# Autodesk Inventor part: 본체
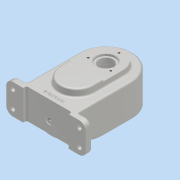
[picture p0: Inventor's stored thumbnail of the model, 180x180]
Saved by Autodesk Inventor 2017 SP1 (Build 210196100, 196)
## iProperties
Part Number: 본체
Material: 알루미늄 6061
Document SubType Name: Modeling
Designer: MRC
Density: 2.7 g/cm^3
Appearance: 알루미늄 - 평지
Mass: 756.756 g
Surface Area: 581.797 cm^2
Volume: 280.28 cm^3
Author: MRC
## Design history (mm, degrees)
sketch "스케치14"
  geometry: L1 (0, 0)-(0, -45); L2 (-40, 0)-(-40, -45); L3 (40, -45)-(40, 0); L4 (0, 0)-(45, 0); L5 (40, -45)-(40, -82); L6 (40, -82)-(61, -82); L7 (61, -82)-(61, -92); L8 (61, -92)-(-61, -92); L9 (-61, -92)-(-61, -82); L10 (-61, -82)-(-40, -82); L11 (-40, -82)-(-40, -45); A1 r 40 centre (0, 0) between (40, 0) and (-40, 0); A2 r 40 centre (0, -45) between (-40, -45) and (40, -45); 1 further point
  constraints: 24 end point, 5 tangent, 4 perpendicular, 4 point on circle, 2 centre point, 2 equal length, 2 point on line, 2 vertical, 1 collinear, 1 horizontal, 1 midpoint, 1 parallel
  dimensions: "d58" = 45 distance of L1.start L1.end; "d59" = 90 deg angle of L1 L4 (derived); "d60" = 80 diameter of A2; "d61" = 47 distance from line of L8 L1.end; "d62" = 122 distance of L7.end L8.end; "d63" = 10 distance of L6.end L7.end
extrude "돌출11" new body sketch "스케치14" distance "d64" = 46; taper "d65" = 0 deg
sketch "스케치15"
  geometry: L1 (0, 0)-(0, -45); L2 (-40, 0)-(-40, -45); L3 (40, -45)-(40, 0); A1 r 40 centre (0, 0) between (40, 0) and (-40, 0) reference; A2 r 40 centre (0, 0) between (40, 0) and (-40, 0); A3 r 40 centre (0, -45) between (-40, -45) and (40, -45); 1 further point
  constraints: 8 end point, 4 point on circle, 4 tangent, 2 centre point, 1 midpoint, 1 parallel, 1 vertical
  dimensions: "d66" = 45 distance of L1.start L1.end; "d67" = 40 radius of A3
extrude "돌출12" join sketch "스케치15" distance "d68" = 3; taper "d69" = 0 deg
sketch "스케치16"
  geometry: L1 (0, 0)-(0, -45); L2 (-30, 0)-(-30, -45); L3 (30, -45)-(30, 0); A1 r 40 centre (0, -45) between (-40, -45) and (40, -45) reference; A2 r 40 centre (0, 0) between (40, 0) and (-40, 0) reference; A3 r 30 centre (0, 0) between (30, 0) and (-30, 0); A4 r 30 centre (0, -45) between (-30, -45) and (30, -45); 1 further point
  constraints: 8 end point, 4 point on circle, 4 tangent, 2 centre point, 1 midpoint, 1 parallel, 1 vertical
  dimensions: "d70" = 30 radius of A3
extrude "돌출13" cut sketch "스케치16" distance "d71" = 41; taper "d72" = 0 deg
sketch "스케치17"
  geometry: L1 (0, 0)-(0, -45); L2 (-26, 0)-(-26, -45); L3 (26, -45)-(26, 0); A1 r 40 centre (0, 0) between (40, 0) and (-40, 0) reference; A2 r 26 centre (0, 0) between (26, 0) and (-26, 0); A3 r 26 centre (0, -45) between (-26, -45) and (26, -45); 1 further point
  constraints: 8 end point, 4 point on circle, 4 tangent, 2 centre point, 1 midpoint, 1 parallel, 1 vertical
  dimensions: "d73" = 45 distance of L1.start L1.end; "d74" = 52 diameter of A3
extrude "돌출14" join sketch "스케치17" distance "d75" = 11; taper "d76" = 0 deg
sketch "스케치18"
  geometry: L1 (-26, 0)-(-26, -45) reference; L2 (26, -45)-(26, 0) reference; L3 (-26, -30)-(26, -30); A1 r 26 centre (0, 0) between (26, 0) and (-26, 0) reference
  constraints: 2 end point, 2 point on line, 1 perpendicular
  dimensions: "d77" = 30 distance from line of A1.centre L3
extrude "돌출15" cut sketch "스케치18" distance "d78" = 3; taper "d79" = 0 deg
hole "구멍1" diameter "d82" = 22; stored, may be unused: countersink angle "d86" = 90 deg, drill point angle "d88" = 118 deg; dims "d80" = 10, "d81" = 10, "d83" = 6, "d84" = 28, "d85" = 8, "d87" = 8
hole "구멍2" diameter "d91" = 20; stored, may be unused: countersink angle "d95" = 90 deg, drill point angle "d97" = 0 deg; dims "d89" = 10, "d90" = 10, "d92" = 6, "d93" = 28, "d94" = 8, "d96" = 12
sketch "스케치19"
  geometry: C1 r 11 at (0, 0) reference; C2 r 14 at (0, 0); A1 r 26 centre (0, 0) between (26, 0) and (-26, 0) reference
  constraints: 1 centre point, 1 coincident
  dimensions: "d98" = 28 diameter of C2
extrude "돌출16" cut sketch "스케치19" distance "d99" = 4; taper "d100" = 0 deg
chamfer "모따기4" distance "d101" = 1; stored, may be unused: second distance "d102" = 2, angle "d103" = 45 deg
fillet "모깎기5" dims "d104" = 0.3
fillet "모깎기6" dims "d105" = 3
sketch "스케치20"
  geometry: A1 r 30 centre (0, 0) between (30, 0) and (-30, 0) reference; 1 further point
  constraints: 1 vertical alignment
  dimensions: "d106" = 35 distance of A1.centre point (0, 35)
sketch "스케치21"
  geometry: A1 r 30 centre (0, -45) between (-30, -45) and (30, -45) reference; 1 further point
  constraints: 1 vertical alignment
  dimensions: "d107" = 35 distance of A1.centre point (0, -80)
hole "구멍3" sketch "스케치20" diameter "d108" = 3.242; stored, may be unused: countersink angle "d112" = 90 deg, drill point angle "d114" = 118 deg; dims "d109" = 8, "d110" = 28, "d111" = 8, "d113" = 10
hole "구멍4" sketch "스케치21" diameter "d115" = 3.242; stored, may be unused: countersink angle "d119" = 90 deg, drill point angle "d121" = 118 deg; dims "d116" = 8, "d117" = 28, "d118" = 8, "d120" = 10
fillet "모깎기7" dims "d131" = 10
sketch "스케치22"
  geometry: A1 r 10 centre (-11, 10) between (-21, 10) and (-11, 0) reference; A2 r 10 centre (-11, 36) between (-11, 46) and (-21, 36) reference; 3 further points
  constraints: 2 coincident
hole "구멍5" sketch "스케치22" at (-11, 36), (-11, 10) diameter "d132" = 6.6; stored, may be unused: countersink angle "d136" = 90 deg, drill point angle "d138" = 118 deg; dims "d133" = 8, "d134" = 11, "d135" = 2, "d137" = 10
sketch "스케치23"
  geometry: A1 r 26 centre (0, 0) between (26, 0) and (-26, 0) reference; 1 further point
  constraints: 1 vertical alignment
  dimensions: "d139" = 20 distance of A1.centre point (0, 20)
hole "구멍6" sketch "스케치23" at (0, 20) diameter "d140" = 3.242; stored, may be unused: countersink angle "d144" = 90 deg, drill point angle "d146" = 118 deg; dims "d141" = 8, "d142" = 11, "d143" = 2, "d145" = 10
fillet "모깎기8" dims "d150" = 3
sketch "스케치24"
  geometry: L1 (-51, -92)-(51, -92) reference; L2 (-35, -87)-(35, -87); L3 (35, -87)-(35, -92); L4 (35, -92)-(-35, -92); L5 (-35, -92)-(-35, -87); 2 further points
  constraints: 8 end point, 2 midpoint, 2 parallel, 1 horizontal, 1 perpendicular
  dimensions: "d151" = 70 distance of L3.end L4.end; "d152" = 5 distance of L2.end L3.end
extrude "돌출17" cut sketch "스케치24" stored distance "d153" = 4; taper "d154" = 0 deg
fillet "모깎기9" dims "d155" = 3
fillet "모깎기10" dims "d156" = 5
node "작업 평면1"
sketch "스케치25"
  geometry: L1 (-40, -49)-(40, -49) reference; C1 r 6 at (0, -28); 1 further point
  constraints: 1 centre point, 1 vertical alignment
  dimensions: "d158" = 12 diameter of C1; "d159" = 21 distance from line of C1.centre L1
extrude "돌출18" join sketch "스케치25" stored distance "d160" = 4; taper "d161" = 0 deg
fillet "모깎기11" dims "d162" = 3
sketch "스케치26"
  geometry: L1 (0, 46)-(64, 46) reference; L2 (-8, -3)-(72, -3) reference; C1 r 6 at (32, 18); 2 further points
  constraints: 1 centre point, 1 midpoint, 1 vertical alignment
  dimensions: "d172" = 12 diameter of C1; "d173" = 21 distance from line of C1.centre L2
extrude "돌출19" cut sketch "스케치26" distance "d174" = 1; taper "d175" = 0 deg
hole "구멍8" diameter "d178" = 4.917; stored, may be unused: countersink angle "d182" = 90 deg, drill point angle "d184" = 118 deg; dims "d176" = 10, "d177" = 10, "d179" = 12, "d180" = 11, "d181" = 2, "d183" = 17.1
sketch "스케치27"
  geometry: L1 (-32, -87)-(32, -87) reference; L2 (-51, -92)-(-61, -92) reference; 2 further points
  constraints: 1 midpoint, 1 vertical alignment, 1 other
  dimensions: "d186" = 12 distance from line of point (0, -80) L2
feature "엠보싱1" sketch "스케치27" dims "d66" = 45, "d67" = 40, "d187" = 0.5, "d188" = 0
sketch "스케치28"
  geometry: A1 r 6 centre (0, 28) between (0, 34) and (0, 22) reference; 1 further point
hole "구멍9" sketch "스케치28" at (0, 28) diameter "d189" = 4.917; stored, may be unused: countersink angle "d193" = 90 deg, drill point angle "d195" = 118 deg; dims "d190" = 12, "d191" = 11, "d192" = 2, "d194" = 25.6
node "솔리드2"
pattern_circular "원형 패턴2" dims angle "d126" = 180 deg
pattern_circular "원형 패턴3" dims angle "d129" = 180 deg
mirror "미러1"
pattern_circular "원형 패턴4" dims angle "d148" = 360 deg
other parameters: "d157" = 43
